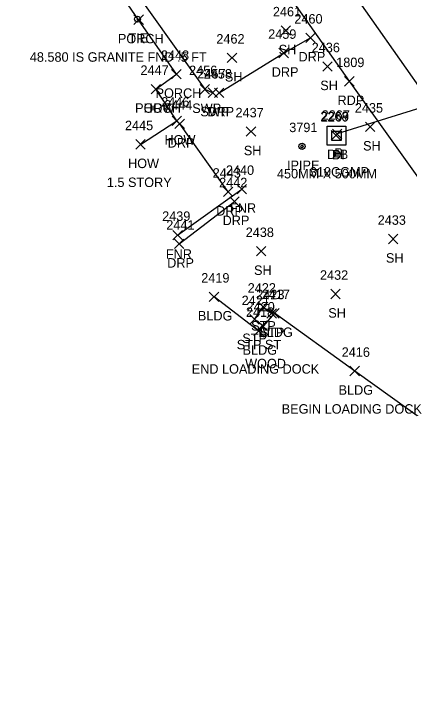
# Model space of a CAD drawing. Extents: x 1634209 to 1639641, y 608564 to 612258.
# Drawn here: x 1638940.8 to 1639024.2, y 611313.4 to 611460.6 of the extents above; entities that cross this region are included whole.
import ezdxf

# ---------------------------------------------------------------- set-up
doc = ezdxf.new("R2010")
doc.units = 0
for name, color, linetype in [('C_A', 7, 'Continuous'), ('C_C', 7, 'Continuous'), ('CBP', 7, 'Continuous'), ('D_A', 7, 'Continuous'), ('D_C', 7, 'Continuous'), ('D_I', 7, 'Continuous'), ('D_TIC', 7, 'Continuous'), ('DCP', 7, 'Continuous'), ('DS', 7, 'Continuous'), ('L_A', 7, 'Continuous'), ('L_C', 7, 'Continuous'), ('L_I', 7, 'Continuous'), ('L_TIC', 7, 'Continuous'), ('LBC', 7, 'Continuous'), ('LBF', 7, 'Continuous'), ('LFNC', 7, 'Continuous'), ('M_A', 7, 'Continuous'), ('M_I', 7, 'Continuous'), ('MPIP', 7, 'Continuous'), ('P_A', 7, 'Continuous'), ('P_I', 7, 'Continuous'), ('P_TIC', 7, 'Continuous'), ('PET', 7, 'Continuous'), ('PRC', 7, 'Continuous'), ('R_A', 7, 'Continuous'), ('R_I', 7, 'Continuous'), ('R_TIC', 7, 'Continuous'), ('RDP', 7, 'Continuous'), ('RSW', 7, 'Continuous')]:
    doc.layers.add(name, color=color, linetype=linetype)

msp = doc.modelspace()

# ---------------------------------------------------------------- linework, layer by layer
at = {"layer": 'CBP'}
for radius in [0.625, 0.0833]:
    msp.add_circle((1638966.89, 611459.53), radius, dxfattribs=at)
at = {"layer": 'D_TIC'}
for points in [[(1639008.01, 611434.28), (1639010.01, 611436.28)], [(1639010.01, 611434.28), (1639008.01, 611436.28)], [(1639007.76, 611434), (1639009.76, 611436)], [(1639009.76, 611434), (1639007.76, 611436)]]:
    msp.add_lwpolyline(points, dxfattribs=at)
at = {"layer": 'DCP'}
msp.add_lwpolyline([(1639040.23, 611445.04), (1639009.01, 611435.28)], dxfattribs=at)
at = {"layer": 'DS'}
for p, q in [((1639006.85, 611436.9), (1639010.85, 611436.9)), ((1639006.85, 611432.9), (1639006.85, 611436.9)), ((1639010.85, 611436.9), (1639010.85, 611432.9)), ((1639007.85, 611433.9), (1639007.85, 611435.9)), ((1639007.85, 611435.9), (1639009.85, 611435.9)), ((1639008.85, 611434.9), (1639008.85, 611434.9)), ((1639008.85, 611434.9), (1639008.85, 611434.9)), ((1639009.85, 611435.9), (1639009.85, 611433.9)), ((1639009.85, 611433.9), (1639007.85, 611433.9)), ((1639010.85, 611432.9), (1639006.85, 611432.9))]:
    msp.add_line(p, q, dxfattribs=at)
at = {"layer": 'L_TIC'}
for points in [[(1638966.11, 611458.41), (1638968.11, 611460.41)], [(1638968.11, 611458.41), (1638966.11, 611460.41)], [(1638997.17, 611456.11), (1638999.17, 611458.11)], [(1638999.17, 611456.11), (1638997.17, 611458.11)], [(1638985.82, 611450.36), (1638987.82, 611452.36)], [(1638987.82, 611450.36), (1638985.82, 611452.36)], [(1639005.94, 611448.54), (1639007.94, 611450.54)], [(1639007.94, 611448.54), (1639005.94, 611450.54)], [(1638974.07, 611446.91), (1638976.07, 611448.91)], [(1638976.07, 611446.91), (1638974.07, 611448.91)], [(1638969.75, 611443.75), (1638971.75, 611445.75)], [(1638971.75, 611443.75), (1638969.75, 611445.75)], [(1638969.75, 611443.75), (1638971.75, 611445.75)], [(1638971.75, 611443.75), (1638969.75, 611445.75)], [(1638974.17, 611437.04), (1638976.17, 611439.04)], [(1638976.17, 611437.04), (1638974.17, 611439.04)], [(1639014.97, 611435.79), (1639016.97, 611437.79)], [(1639016.97, 611435.79), (1639014.97, 611437.79)], [(1638989.81, 611434.79), (1638991.81, 611436.79)], [(1638991.81, 611434.79), (1638989.81, 611436.79)], [(1638966.49, 611432.08), (1638968.49, 611434.08)], [(1638968.49, 611432.08), (1638966.49, 611434.08)], [(1638987.87, 611422.64), (1638989.87, 611424.64)], [(1638989.87, 611422.64), (1638987.87, 611424.64)], [(1638974.33, 611412.93), (1638976.33, 611414.93)], [(1638976.33, 611412.93), (1638974.33, 611414.93)], [(1639019.8, 611412.11), (1639021.8, 611414.11)], [(1639021.8, 611412.11), (1639019.8, 611414.11)], [(1638991.96, 611409.52), (1638993.96, 611411.52)], [(1638993.96, 611409.52), (1638991.96, 611411.52)], [(1639007.63, 611400.5), (1639009.63, 611402.5)], [(1639009.63, 611400.5), (1639007.63, 611402.5)], [(1638982.02, 611399.9), (1638984.02, 611401.9)], [(1638984.02, 611399.9), (1638982.02, 611401.9)], [(1638992.38, 611397.78), (1638994.38, 611399.78)], [(1638994.38, 611397.78), (1638992.38, 611399.78)], [(1638994.19, 611396.39), (1638996.19, 611398.39)], [(1638996.19, 611396.39), (1638994.19, 611398.39)], [(1638994.76, 611396.42), (1638996.76, 611398.42)], [(1638996.76, 611396.42), (1638994.76, 611398.42)], [(1638990.54, 611395.14), (1638992.54, 611397.14)], [(1638992.54, 611395.14), (1638990.54, 611397.14)], [(1638992.22, 611393.81), (1638994.22, 611395.81)], [(1638994.22, 611393.81), (1638992.22, 611395.81)], [(1638991.44, 611392.67), (1638993.44, 611394.67)], [(1638993.44, 611392.67), (1638991.44, 611394.67)], [(1639011.7, 611384.23), (1639013.7, 611386.23)], [(1639013.7, 611384.23), (1639011.7, 611386.23)]]:
    msp.add_lwpolyline(points, dxfattribs=at)
at = {"layer": 'LBC'}
for points in [[(1638967.49, 611433.08), (1638975.17, 611438.04), (1638970.75, 611444.75)], [(1639030.18, 611240.11), (1639055, 611274.11), (1639074.75, 611301.09), (1639056.77, 611314.91), (1639059.81, 611319.01), (1639041.02, 611332.86), (1639050.68, 611345.89), (1639051.33, 611346.8), (1639056.15, 611353.65), (1639047.24, 611360), (1639049.34, 611363.02), (1639049.78, 611363.31), (1639052.47, 611367.11), (1639048.07, 611370.37), (1639042.99, 611363.34), (1639028.13, 611374.15), (1639012.7, 611385.23), (1638995.76, 611397.42), (1638992.44, 611393.67), (1638983.02, 611400.9)]]:
    msp.add_lwpolyline(points, dxfattribs=at)
at = {"layer": 'LBF'}
for points in [[(1638970.75, 611444.75), (1638975.07, 611447.91), (1638967.11, 611459.41), (1638958.38, 611472.15), (1638953.36, 611468.83), (1638948.31, 611476.6)], [(1638993.22, 611394.81), (1638991.54, 611396.14), (1638993.38, 611398.78), (1638995.19, 611397.39)]]:
    msp.add_lwpolyline(points, dxfattribs=at)
at = {"layer": 'LFNC'}
msp.add_lwpolyline([(1638975.33, 611413.93), (1638988.87, 611423.64)], dxfattribs=at)
at = {"layer": 'MPIP'}
msp.add_lwpolyline([(1639001.91, 611432.67), (1639001.58, 611433), (1639001.24, 611432.67), (1639001.58, 611432.33)], close=True, dxfattribs=at)
msp.add_circle((1639001.58, 611432.67), 0.667, dxfattribs=at)
at = {"layer": 'P_TIC'}
for points in [[(1639010.57, 611445.4), (1639012.57, 611447.4)], [(1639012.57, 611445.4), (1639010.57, 611447.4)]]:
    msp.add_lwpolyline(points, dxfattribs=at)
at = {"layer": 'PET'}
msp.add_lwpolyline([(1639117.36, 611283.37), (1639114.12, 611301.89), (1639095.51, 611328.5), (1639070.51, 611363.26), (1639041.38, 611404.69), (1639011.57, 611446.4), (1638984.33, 611485.14), (1638954.17, 611527.49), (1638934.32, 611554.77), (1638918.88, 611575.58), (1638893.27, 611605.66), (1638868.11, 611629.83), (1638836.66, 611652.85), (1638812.43, 611667.63)], dxfattribs=at)
at = {"layer": 'PRC'}
msp.add_lwpolyline([(1638818.79, 611678.83), (1638843.97, 611663.34), (1638876.43, 611637.38), (1638906.24, 611607.19), (1638934.14, 611573.69), (1638965.3, 611531.42), (1638998.82, 611484.34), (1639033.82, 611434.48), (1639068.01, 611386.3), (1639093.94, 611350.49), (1639111.89, 611325.37), (1639129.22, 611302.76)], dxfattribs=at)
at = {"layer": 'R_TIC'}
for points in [[(1639002.35, 611454.59), (1639004.35, 611456.59)], [(1639004.35, 611454.59), (1639002.35, 611456.59)], [(1638996.7, 611451.37), (1638998.7, 611453.37)], [(1638998.7, 611451.37), (1638996.7, 611453.37)], [(1638980.06, 611443.71), (1638982.06, 611445.71)], [(1638982.06, 611443.71), (1638980.06, 611445.71)], [(1638981.76, 611443), (1638983.76, 611445)], [(1638983.76, 611443), (1638981.76, 611445)], [(1638983.11, 611442.98), (1638985.11, 611444.98)], [(1638985.11, 611442.98), (1638983.11, 611444.98)], [(1638974.77, 611436.41), (1638976.77, 611438.41)], [(1638976.77, 611436.41), (1638974.77, 611438.41)], [(1638984.98, 611422.05), (1638986.98, 611424.05)], [(1638986.98, 611422.05), (1638984.98, 611424.05)], [(1638986.34, 611420.03), (1638988.34, 611422.03)], [(1638988.34, 611420.03), (1638986.34, 611422.03)], [(1638974.65, 611411.07), (1638976.65, 611413.07)], [(1638976.65, 611411.07), (1638974.65, 611413.07)]]:
    msp.add_lwpolyline(points, dxfattribs=at)
at = {"layer": 'RDP'}
for points in [[(1638984.11, 611443.98), (1638997.7, 611452.37), (1639003.35, 611455.59)], [(1638985.98, 611423.05), (1638975.77, 611437.41)], [(1638975.65, 611412.07), (1638987.34, 611421.03)]]:
    msp.add_lwpolyline(points, dxfattribs=at)
at = {"layer": 'RSW'}
msp.add_lwpolyline([(1638949.07, 611476.9), (1638955.12, 611480.86), (1638963.04, 611470.11), (1638981.06, 611444.71), (1638982.76, 611444)], dxfattribs=at)

# ---------------------------------------------------------------- texts
at = {"layer": 'C_A'}
msp.add_text('TIE', height=2, dxfattribs=at).set_placement((1638964.97, 611454.53))
at = {"layer": 'C_C'}
msp.add_text('48.580 IS GRANITE FND .5 FT', height=2, dxfattribs=at).set_placement((1638944.16, 611450.53))
at = {"layer": 'D_A'}
for s, p in [('DIB', (1639006.86, 611430)), ('DI', (1639007.91, 611429.9)), ('P', (1639008.39, 611430.28))]:
    msp.add_text(s, height=2, dxfattribs=at).set_placement(p)
at = {"layer": 'D_C'}
for s, p in [('450MM X 500MM', (1638996.29, 611425.9)), ('310CGMP', (1639003.23, 611426.28))]:
    msp.add_text(s, height=2, dxfattribs=at).set_placement(p)
at = {"layer": 'D_I'}
for s, p in [('2268', (1639005.45, 611438)), ('2269', (1639005.54, 611437.9)), ('2267', (1639005.71, 611438.28))]:
    msp.add_text(s, height=2, dxfattribs=at).set_placement(p)
at = {"layer": 'L_A'}
for s, p in [('PORCH', (1638962.73, 611454.41)), ('SH', (1638996.66, 611452.11)), ('SH', (1638985.31, 611446.36)), ('SH', (1639005.43, 611444.54)), ('PORCH', (1638970.69, 611442.91)), ('PORCH', (1638966.37, 611439.75)), ('HOW', (1638968.13, 611439.75)), ('HOW', (1638972.56, 611433.04)), ('SH', (1639014.46, 611431.79)), ('SH', (1638989.3, 611430.79)), ('HOW', (1638964.88, 611428.08)), ('FNR', (1638986.4, 611418.64)), ('FNR', (1638972.87, 611408.93)), ('SH', (1639019.28, 611408.11)), ('SH', (1638991.45, 611405.52)), ('BLDG', (1638979.61, 611395.9)), ('SH', (1639007.12, 611396.5)), ('STP', (1638990.84, 611393.78)), ('BLDG', (1638992.36, 611392.42)), ('STP', (1638992.65, 611392.39)), ('STP', (1638988.99, 611391.14)), ('STP ST', (1638987.81, 611389.81)), ('BLDG', (1638989.03, 611388.67)), ('BLDG', (1639009.29, 611380.23))]:
    msp.add_text(s, height=2, dxfattribs=at).set_placement(p)
at = {"layer": 'L_C'}
for s, p in [('1.5 STORY', (1638960.41, 611424.08)), ('WOOD', (1638989.58, 611385.81)), ('END LOADING DOCK', (1638978.31, 611384.67)), ('BEGIN LOADING DOCK', (1638997.29, 611376.23))]:
    msp.add_text(s, height=2, dxfattribs=at).set_placement(p)
at = {"layer": 'L_I'}
for s, p in [('2461', (1638995.43, 611460.11)), ('2462', (1638983.51, 611454.36)), ('2436', (1639003.62, 611452.54)), ('2448', (1638971.81, 611450.91)), ('2447', (1638967.49, 611447.75)), ('2447', (1638967.49, 611447.75)), ('2446', (1638971.86, 611441.04)), ('2437', (1638987.55, 611438.79)), ('2435', (1639012.72, 611439.79)), ('2445', (1638964.23, 611436.08)), ('2440', (1638985.52, 611426.64)), ('2439', (1638972.07, 611416.93)), ('2433', (1639017.54, 611416.11)), ('2438', (1638989.7, 611413.52)), ('2419', (1638980.32, 611403.9)), ('2432', (1639005.37, 611404.5)), ('2422', (1638990.12, 611401.78)), ('2423', (1638991.93, 611400.39)), ('2417', (1638993.07, 611400.42)), ('2421', (1638988.84, 611399.14)), ('2420', (1638989.88, 611397.81)), ('2418', (1638989.74, 611396.67)), ('2416', (1639009.95, 611388.23))]:
    msp.add_text(s, height=2, dxfattribs=at).set_placement(p)
at = {"layer": 'M_A'}
msp.add_text('IPIPE', height=2, dxfattribs=at).set_placement((1638998.41, 611427.67))
at = {"layer": 'M_I'}
msp.add_text('3791', height=2, dxfattribs=at).set_placement((1638998.88, 611435.67))
at = {"layer": 'P_A'}
msp.add_text('RDP', height=2, dxfattribs=at).set_placement((1639009.06, 611441.4))
at = {"layer": 'P_I'}
msp.add_text('1809', height=2, dxfattribs=at).set_placement((1639008.79, 611449.4))
at = {"layer": 'R_A'}
for s, p in [('DRP', (1639000.84, 611450.59)), ('DRP', (1638995.19, 611447.37)), ('SWP', (1638978.42, 611439.71)), ('SWP', (1638980.12, 611439)), ('DRP', (1638981.6, 611438.98)), ('DRP', (1638973.26, 611432.41)), ('DRP', (1638983.47, 611418.05)), ('DRP', (1638984.83, 611416.03)), ('DRP', (1638973.13, 611407.07))]:
    msp.add_text(s, height=2, dxfattribs=at).set_placement(p)
at = {"layer": 'R_I'}
for s, p in [('2460', (1638999.96, 611458.59)), ('2459', (1638994.44, 611455.37)), ('2456', (1638977.75, 611447.71)), ('2457', (1638979.5, 611447)), ('2458', (1638980.85, 611446.98)), ('2444', (1638972.51, 611440.41)), ('2443', (1638982.73, 611426.05)), ('2442', (1638984.09, 611424.03)), ('2441', (1638972.95, 611415.07))]:
    msp.add_text(s, height=2, dxfattribs=at).set_placement(p)

doc.saveas('drawing.dxf')
